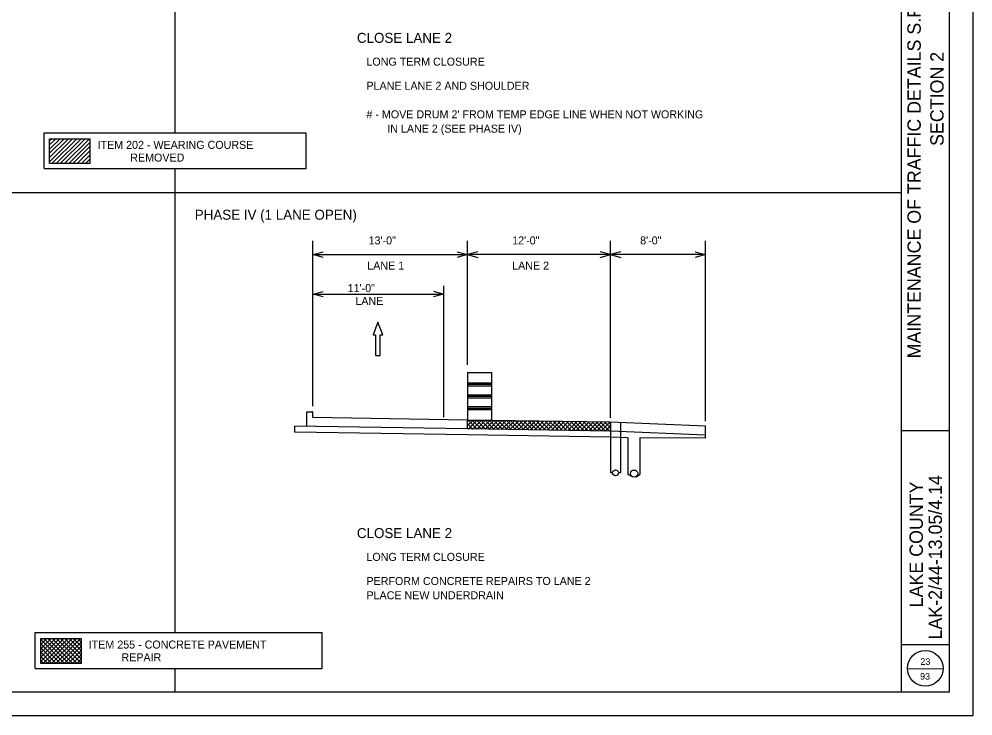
# Model space of a CAD drawing. Extents: x -161 to 291, y -369 to 173.
# Drawn here: x -104.8 to -24.7, y -273.4 to -214.9 of the extents above; entities that cross this region are included whole.
import ezdxf

# ---------------------------------------------------------------- set-up
doc = ezdxf.new("R2010")
doc.units = 0
for name, color, linetype in [('Level 1', 7, 'Continuous'), ('Level 11', 7, 'Continuous'), ('Level 21', 7, 'Continuous'), ('Level 25', 7, 'Continuous'), ('Level 26', 7, 'Continuous'), ('Level 6', 7, 'Continuous'), ('Level 7', 7, 'Continuous')]:
    doc.layers.add(name, color=color, linetype=linetype)

msp = doc.modelspace()

# ---------------------------------------------------------------- linework, layer by layer
at = {"layer": 'Level 1'}
for p, q in [((-24.739, -185.431), (-24.739, -273.422)), ((-91.732, -224.426), (-91.732, -187.43)), ((-26.739, -187.43), (-26.739, -271.422)), ((-30.738, -249.424), (-30.738, -204.429)), ((-102.732, -224.426), (-80.732, -224.426)), ((-102.732, -227.426), (-102.732, -224.426)), ((-80.732, -227.426), (-80.732, -224.426)), ((-102.732, -227.426), (-80.732, -227.426)), ((-91.732, -266.422), (-91.732, -227.426)), ((-152.726, -229.426), (-30.738, -229.426)), ((-30.738, -254.424), (-30.738, -249.424)), ((-30.738, -249.424), (-26.739, -249.424)), ((-30.738, -271.422), (-30.738, -254.424)), ((-103.472, -266.422), (-79.394, -266.422)), ((-103.472, -269.422), (-103.472, -266.422)), ((-79.394, -269.422), (-79.394, -266.422)), ((-103.472, -269.422), (-79.394, -269.422)), ((-91.732, -271.422), (-91.732, -269.422)), ((-26.739, -271.422), (-152.726, -271.422)), ((-24.739, -273.422), (-160.725, -273.422))]:
    msp.add_line(p, q, dxfattribs=at)
at = {"layer": 'Level 11'}
for p, q in [((-102.27, -225.074), (-102.103, -224.908)), ((-102.27, -225.428), (-101.749, -224.908)), ((-102.27, -225.782), (-101.395, -224.908)), ((-102.27, -226.135), (-101.043, -224.908)), ((-102.27, -226.489), (-100.689, -224.908)), ((-102.27, -226.843), (-100.335, -224.908)), ((-102.079, -227.005), (-99.982, -224.908)), ((-101.725, -227.005), (-99.628, -224.908)), ((-101.371, -227.005), (-99.275, -224.908)), ((-101.018, -227.005), (-98.921, -224.908)), ((-100.664, -227.005), (-98.878, -225.219)), ((-100.311, -227.005), (-98.878, -225.572)), ((-99.957, -227.005), (-98.878, -225.926)), ((-99.603, -227.005), (-98.878, -226.279)), ((-99.25, -227.005), (-98.878, -226.633)), ((-80.666, -249.092), (-80.666, -247.851)), ((-80.666, -247.851), (-80.249, -247.851)), ((-80.166, -248.351), (-80.166, -247.934)), ((-67.182, -249.3), (-81.668, -249.076)), ((-81.666, -249.576), (-81.666, -249.076)), ((-67.166, -248.552), (-80.166, -248.351)), ((-67.167, -249.3), (-67.167, -248.552)), ((-55.19, -248.737), (-67.166, -248.552)), ((-47.193, -249.072), (-55.19, -248.737)), ((-55.167, -249.486), (-55.167, -248.738)), ((-47.193, -250.07), (-47.193, -249.072)), ((-67.183, -249.8), (-81.668, -249.576)), ((-55.191, -249.985), (-67.181, -249.8)), ((-55.173, -249.485), (-67.167, -249.3)), ((-47.197, -249.82), (-55.173, -249.485)), ((-53.719, -250.047), (-55.191, -249.985)), ((-53.715, -250.047), (-53.715, -253.138)), ((-47.193, -250.07), (-52.716, -250.05)), ((-52.715, -250.05), (-52.715, -253.128)), ((-53.328, -253.33), (-53.715, -253.138)), ((-53.038, -253.319), (-52.715, -253.127))]:
    msp.add_line(p, q, dxfattribs=at)
msp.add_circle((-53.193, -253.058), 0.304, dxfattribs=at)
msp.add_arc((-80.249, -247.934), 0.083, 0, 90, dxfattribs=at)
at = {"layer": 'Level 21'}
for p, q in [((-67.167, -248.663), (-67.058, -248.554)), ((-67.167, -249.017), (-66.709, -248.559)), ((-67.167, -248.873), (-66.733, -249.307)), ((-67.133, -248.553), (-66.373, -249.312)), ((-67.098, -249.301), (-66.361, -248.565)), ((-66.774, -248.558), (-66.014, -249.318)), ((-66.75, -249.307), (-66.013, -248.57)), ((-66.415, -248.564), (-65.655, -249.324)), ((-66.401, -249.312), (-65.665, -248.575)), ((-66.056, -248.569), (-65.296, -249.329)), ((-66.053, -249.317), (-65.317, -248.581)), ((-65.705, -249.323), (-64.968, -248.586)), ((-65.697, -248.575), (-64.937, -249.335)), ((-65.357, -249.328), (-64.62, -248.592)), ((-65.338, -248.58), (-64.578, -249.34)), ((-65.009, -249.334), (-64.272, -248.597)), ((-64.979, -248.586), (-64.219, -249.346)), ((-64.661, -249.339), (-63.924, -248.602)), ((-64.619, -248.592), (-63.86, -249.351)), ((-64.312, -249.344), (-63.576, -248.608)), ((-64.26, -248.597), (-63.501, -249.357)), ((-63.964, -249.35), (-63.228, -248.613)), ((-63.901, -248.603), (-63.141, -249.362)), ((-63.616, -249.355), (-62.879, -248.618)), ((-63.542, -248.608), (-62.782, -249.368)), ((-63.268, -249.36), (-62.531, -248.624)), ((-63.183, -248.614), (-62.423, -249.374)), ((-62.92, -249.366), (-62.183, -248.629)), ((-62.824, -248.619), (-62.064, -249.379)), ((-62.572, -249.371), (-61.835, -248.635)), ((-62.465, -248.625), (-61.705, -249.385)), ((-62.223, -249.377), (-61.487, -248.64)), ((-62.106, -248.63), (-61.346, -249.39)), ((-61.875, -249.382), (-61.139, -248.645)), ((-61.747, -248.636), (-60.987, -249.396)), ((-61.527, -249.387), (-60.79, -248.651)), ((-61.388, -248.641), (-60.628, -249.401)), ((-61.179, -249.393), (-60.442, -248.656)), ((-61.028, -248.647), (-60.269, -249.407)), ((-60.831, -249.398), (-60.094, -248.661)), ((-60.669, -248.653), (-59.909, -249.412)), ((-60.483, -249.404), (-59.746, -248.667)), ((-60.31, -248.658), (-59.55, -249.418)), ((-60.134, -249.409), (-59.398, -248.672)), ((-59.951, -248.664), (-59.191, -249.424)), ((-59.786, -249.414), (-59.05, -248.678)), ((-59.592, -248.669), (-58.832, -249.429)), ((-59.438, -249.42), (-58.701, -248.683)), ((-59.233, -248.675), (-58.473, -249.435)), ((-59.09, -249.425), (-58.353, -248.688)), ((-58.874, -248.68), (-58.114, -249.44)), ((-58.742, -249.431), (-58.005, -248.694)), ((-58.515, -248.686), (-57.755, -249.446)), ((-58.394, -249.436), (-57.657, -248.699)), ((-58.156, -248.691), (-57.396, -249.451)), ((-58.045, -249.441), (-57.309, -248.704)), ((-57.797, -248.697), (-57.037, -249.457)), ((-57.697, -249.447), (-56.96, -248.71)), ((-57.437, -248.702), (-56.677, -249.462)), ((-57.349, -249.452), (-56.612, -248.715)), ((-57.078, -248.708), (-56.318, -249.468)), ((-57.001, -249.457), (-56.264, -248.721)), ((-56.719, -248.714), (-55.959, -249.474)), ((-56.653, -249.463), (-55.916, -248.726)), ((-56.36, -248.719), (-55.6, -249.479)), ((-56.305, -249.468), (-55.568, -248.731)), ((-56.001, -248.725), (-55.241, -249.485)), ((-55.956, -249.474), (-55.22, -248.737)), ((-55.642, -248.73), (-55.176, -249.197)), ((-55.608, -249.479), (-55.18, -249.051)), ((-55.283, -248.736), (-55.187, -248.831)), ((-55.167, -248.738), (-55.167, -252.986)), ((-54.333, -248.773), (-54.333, -252.986)), ((-67.167, -249.226), (-67.092, -249.301)), ((-55.26, -249.484), (-55.169, -249.394)), ((-55, -252.986), (-55.167, -252.986)), ((-54.333, -252.986), (-54.5, -252.986)), ((-103.01, -267.07), (-102.843, -266.904)), ((-103.01, -267.424), (-102.489, -266.904)), ((-103.01, -267.778), (-102.136, -266.904)), ((-103.01, -268.131), (-101.783, -266.904)), ((-103.01, -268.485), (-101.429, -266.904)), ((-103.01, -268.838), (-101.075, -266.904)), ((-101.014, -269.001), (-103.01, -267.004)), ((-101.367, -269.001), (-103.01, -267.358)), ((-102.819, -269.001), (-100.722, -266.904)), ((-100.66, -269.001), (-102.757, -266.904)), ((-102.465, -269.001), (-100.368, -266.904)), ((-100.307, -269.001), (-102.404, -266.904)), ((-102.111, -269.001), (-100.015, -266.904)), ((-99.953, -269.001), (-102.05, -266.904)), ((-101.758, -269.001), (-99.661, -266.904)), ((-99.618, -268.982), (-101.697, -266.904)), ((-101.404, -269.001), (-99.618, -267.214)), ((-99.618, -268.628), (-101.343, -266.904)), ((-99.618, -268.275), (-100.989, -266.904)), ((-99.618, -267.921), (-100.636, -266.904)), ((-99.618, -267.568), (-100.282, -266.904)), ((-99.618, -267.214), (-99.929, -266.904)), ((-30.738, -267.422), (-26.739, -267.422)), ((-101.721, -269.001), (-103.01, -267.711)), ((-102.074, -269.001), (-103.01, -268.065)), ((-101.051, -269.001), (-99.618, -267.568)), ((-100.697, -269.001), (-99.618, -267.921)), ((-100.344, -269.001), (-99.618, -268.275)), ((-102.428, -269.001), (-103.01, -268.419)), ((-102.782, -269.001), (-103.01, -268.772)), ((-99.991, -269.001), (-99.618, -268.628)), ((-30.239, -269.449), (-27.239, -269.446))]:
    msp.add_line(p, q, dxfattribs=at)
for centre, radius in [((-54.75, -252.986), 0.25), ((-28.738, -269.422), 1.5)]:
    msp.add_circle(centre, radius, dxfattribs=at)
at = {"layer": 'Level 25'}
for p, q in [((-67.166, -244.552), (-67.166, -248.552)), ((-67.166, -244.552), (-65.166, -244.552)), ((-65.166, -244.552), (-65.166, -248.552)), ((-67.166, -245.427), (-65.166, -245.427)), ((-67.166, -245.552), (-65.166, -245.552)), ((-67.166, -245.677), (-65.166, -245.677)), ((-67.166, -246.427), (-65.166, -246.427)), ((-67.166, -246.552), (-65.166, -246.552)), ((-67.166, -246.677), (-65.166, -246.677)), ((-67.166, -247.427), (-65.166, -247.427)), ((-67.166, -247.552), (-65.166, -247.552)), ((-67.166, -247.677), (-65.166, -247.677)), ((-67.166, -248.552), (-65.166, -248.552))]:
    msp.add_line(p, q, dxfattribs=at)
at = {"layer": 'Level 26'}
for p, q in [((-80.167, -247.374), (-80.167, -233.492)), ((-67.167, -243.914), (-67.167, -233.492)), ((-55.167, -248.358), (-55.167, -233.492)), ((-47.193, -248.65), (-47.193, -233.492)), ((-80.167, -234.652), (-67.167, -234.652)), ((-55.167, -234.652), (-67.167, -234.652)), ((-47.193, -234.652), (-55.167, -234.652)), ((-69.167, -248.306), (-69.167, -237.261)), ((-80.167, -237.972), (-69.167, -237.972))]:
    msp.add_line(p, q, dxfattribs=at)
for points in [[(-79.3, -234.891), (-80.167, -234.652), (-79.3, -234.421)], [(-68.033, -234.412), (-67.167, -234.652), (-68.033, -234.883)], [(-66.3, -234.412), (-67.167, -234.652), (-66.3, -234.883)], [(-56.035, -234.891), (-55.167, -234.652), (-56.035, -234.42)], [(-54.3, -234.412), (-55.167, -234.652), (-54.3, -234.883)], [(-48.061, -234.412), (-47.193, -234.652), (-48.061, -234.883)], [(-79.3, -238.211), (-80.167, -237.972), (-79.3, -237.741)], [(-70.033, -237.733), (-69.167, -237.972), (-70.033, -238.203)]]:
    msp.add_lwpolyline(points, dxfattribs=at)
at = {"layer": 'Level 6'}
for points in [[(-102.27, -224.908), (-98.878, -224.908), (-98.878, -227.005), (-102.27, -227.005)], [(-103.01, -266.904), (-99.618, -266.904), (-99.618, -269.001), (-103.01, -269.001)]]:
    msp.add_lwpolyline(points, close=True, dxfattribs=at)
at = {"layer": 'Level 7'}
for p, q in [((-74.7, -240.33), (-75.097, -241.4)), ((-74.297, -241.4), (-74.7, -240.33)), ((-75.097, -241.4), (-74.892, -241.4)), ((-74.892, -241.4), (-74.892, -243.128)), ((-74.502, -243.128), (-74.502, -241.4)), ((-74.502, -241.4), (-74.297, -241.4)), ((-74.892, -243.128), (-74.502, -243.128))]:
    msp.add_line(p, q, dxfattribs=at)

# ---------------------------------------------------------------- texts
at = {"layer": 'Level 1'}
for s, height, p in [('MAINTENANCE OF TRAFFIC DETAILS S.R. - 44', 1.11989, (-29.118, -243.372)), ('SECTION 2', 1.1199, (-27.198, -225.515)), ('LAKE COUNTY', 1.11989, (-28.941, -264.292)), ('LAK-2/44-13.05/4.14', 1.11989, (-27.341, -266.998))]:
    msp.add_text(s, height=height, rotation=90, dxfattribs=at).set_placement(p)
for s, p in [('23', (-29.148, -269.131)), ('93', (-29.174, -270.373))]:
    msp.add_text(s, height=0.5599, dxfattribs=at).set_placement(p)
at = {"layer": 'Level 26'}
for s, p in [('13\'-0"', (-75.485, -233.794)), ('12\'-0"', (-63.428, -233.794)), ('8\'-0"', (-52.683, -233.794)), ('LANE 1', (-75.596, -235.911)), ('LANE 2', (-63.428, -235.911)), ('11\'-0"', (-77.242, -237.804)), ('LANE', (-76.596, -238.876))]:
    msp.add_text(s, height=0.672, dxfattribs=at).set_placement(p)
at = {"layer": 'Level 6'}
for s, height, p in [('CLOSE LANE 2', 0.84, (-76.464, -216.854)), ('LONG TERM CLOSURE', 0.672, (-75.664, -218.77)), ('PLANE LANE 2 AND SHOULDER', 0.672, (-75.664, -220.798)), ("# - MOVE DRUM 2' FROM TEMP EDGE LINE WHEN NOT WORKING", 0.672, (-75.664, -223.198)), ('       IN LANE 2 (SEE PHASE IV)', 0.672, (-75.664, -224.398)), ('ITEM 202 - WEARING COURSE', 0.672, (-98.242, -225.762)), ('           REMOVED', 0.672, (-98.242, -226.834)), ('PHASE IV (1 LANE OPEN)', 0.84, (-90.082, -231.718)), ('CLOSE LANE 2', 0.84, (-76.464, -258.474)), ('LONG TERM CLOSURE', 0.672, (-75.664, -260.39)), ('PERFORM CONCRETE REPAIRS TO LANE 2', 0.672, (-75.664, -262.418)), ('PLACE NEW UNDERDRAIN ', 0.672, (-75.664, -263.617)), ('ITEM 255 - CONCRETE PAVEMENT', 0.672, (-98.982, -267.758)), ('           REPAIR', 0.672, (-98.982, -268.83))]:
    msp.add_text(s, height=height, dxfattribs=at).set_placement(p)

doc.saveas('drawing.dxf')
